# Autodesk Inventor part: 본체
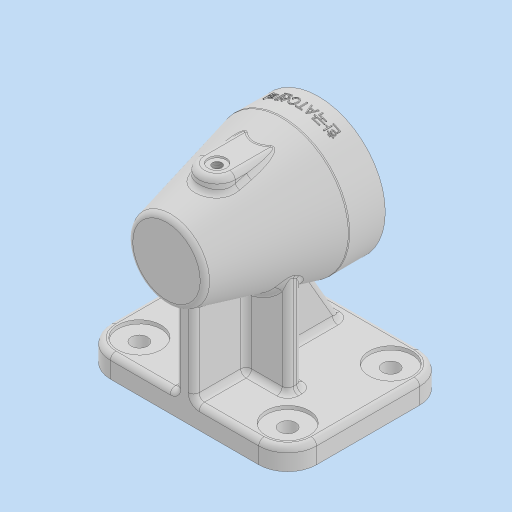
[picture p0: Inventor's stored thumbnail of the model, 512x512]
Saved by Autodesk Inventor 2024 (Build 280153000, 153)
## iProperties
Created: 2024-12
Part Number: 본체
Material: 일반
Document SubType Name: Modeling
Designer: user
Density: 1 g/cm^3
Appearance: 기본값
Author: user
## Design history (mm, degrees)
sketch "스케치11"
  geometry: L1 (0, 42)-(0, -42); L2 (0, 42)-(21, 42); L3 (21, 42)-(37, -22); L4 (37, -22)-(37, -42); L5 (37, -42)-(24.5, -42); L6 (23.5, -41)-(23.5, -24); L7 (23.5, -24)-(25.743, -24); L8 (30.606, -17.837)-(21.871, 18.698); L9 (18.953, 21)-(18.5, 21); L10 (17.5, 22)-(17.5, 30.7); L11 (17.2, 31)-(15.5, 31); L12 (15.5, 31)-(15.5, 31); L13 (12.5, 34)-(0, 34); L14 (17.5, 22)-(18.5, 21); L15 (23.5, -41)-(24.5, -42); L16 (24.5, -42)-(0, -42); A1 r 5 centre (25.743, -19) between (25.743, -24) and (30.606, -17.837); A2 r 0.3 centre (17.2, 30.7) between (17.5, 30.7) and (17.2, 31); A3 r 3 centre (18.953, 18) between (21.871, 18.698) and (18.953, 21); A4 r 3 centre (12.5, 31) between (15.5, 31) and (12.5, 34); 12 further points
  constraints: 32 end point, 8 perpendicular, 8 point on circle, 8 point on line, 8 tangent, 7 midpoint, 4 centre point, 2 vertical, 1 coincident, 1 horizontal, 1 parallel
  dimensions: "d29" = 84 distance of L1.start L1.end; "d30" = 74 diameter of L4 L1; "d31" = 42 diameter of L2.end L1; "d32" = 20 distance of L3.end L4.end; "d52" = 47 diameter of L6 L1; "d53" = 5 radius of A1; "d54" = 18 distance of point (23.5, -42) L6.end; "d56" = 35 diameter of point (17.5, 26.35) L1; "d57" = 31 diameter of point (15.5, 31) L1; "d58" = 0.3 radius of A2; "d59" = 10 distance from line of L9 point (16.35, 31); "d60" = 3 distance between parallel lines of L13 L11; "d62" = 3 radius of A3; "d63" = 5 distance from line of L3 point (26.239, 0.43); "d65" = 45 distance between parallel lines of L7 L9; "d66" = 3 radius of A4 (derived); "d67" = 1 distance of L10.start point (17.5, 21); "d68" = 1 distance of L9.end point (17.5, 21) (= d67); "d69" = 13.4469 deg angle of L1 L8; "d70" = 1 distance of L6.start point (23.5, -42); "d71" = 1 distance of L5.end point (23.5, -42) (= d70)
revolve "회전1" stored, may be unused: angle "d33" = 90 deg
node "작업 평면5"
sketch "스케치12"
  geometry: L1 (57, -57)-(-57, -57); L2 (-57, -57)-(-57, 32); L3 (-57, 32)-(57, 32); L4 (57, 32)-(57, -57); L5 (-37, -42)-(37, -42) reference; 2 further points
  constraints: 8 end point, 2 parallel, 1 horizontal, 1 midpoint, 1 perpendicular, 1 vertical alignment
  dimensions: "d35" = 15 distance between parallel lines of L5 L1; "d36" = 114 distance between parallel lines of L2 L4; "d37" = 89 distance of L1.end L2.end
extrude "돌출5" join sketch "스케치12" distance "d38" = 12; taper "d39" = 0 deg
revolve "회전2" stored, may be unused: angle "d72" = 90 deg
sketch "스케치18"
  geometry: L1 (-57, -32)-(57, -32) reference; L2 (-28, -3)-(28, -3); L3 (28, -3)-(28, 5); L4 (28, 5)-(-28, 5); L5 (-28, 5)-(-28, -3); 2 further points
  constraints: 8 end point, 2 parallel, 1 horizontal, 1 midpoint, 1 perpendicular, 1 vertical alignment
  dimensions: "d75" = 8 distance of L4.end L2.start; "d76" = 56 distance of L3.end L4.end; "d77" = 29 distance between parallel lines of L1 L2
extrude "돌출7" join sketch "스케치18" stored distance "d78" = 18; taper "d79" = 0 deg
sketch "스케치19"
  geometry: L1 (-37, -30.947)-(-70, -50); L2 (-70, -57)-(-70, 32) reference; L3 (-37, -22)-(-37, -42) reference; 1 further point
  constraints: 2 end point, 2 point on line
  dimensions: "d80" = 7 distance of L1.end L2.start; "d81" = 60 deg angle of L2 L1
feature "리브1" sketch "스케치19" dims "d82" = 1, "d83" = 10, "d84" = 0, "d85" = 0, "d86" = 1, "d87" = 1
sketch "스케치20"
  geometry: L1 (-82, 32)-(-70, 32) reference; L2 (-70, 32)-(-23.5, 32); L3 (-21, 42)-(-30.75, 3) reference; 1 further point
  constraints: 2 end point, 1 horizontal, 1 point on line
feature "리브2" sketch "스케치20" dims "d88" = 1, "d89" = 10, "d90" = 0, "d91" = 0, "d92" = 1, "d93" = 1
sketch "스케치21" dims "d94" = 57
  geometry: C1 r 24.5 at (0, 0) reference; C2 r 37 at (0, 0) reference; 2 further points
  constraints: 2 vertical alignment, 1 coincident, 2 other
hole "구멍1" sketch "스케치21" at (0, 28.5) diameter "d95" = 3.242; stored, may be unused: countersink angle "d99" = 90 deg, drill point angle "d101" = 118 deg; dims "d96" = 8, "d97" = 4, "d98" = 2, "d100" = 10
node "작업 평면6"
sketch "스케치22"
  geometry: L1 (-37, -42)-(37, -42) reference; L2 (16.733, -22)-(16.733, -42) reference; L3 (16.733, -42)-(-16.733, -42) reference; L4 (-16.733, -42)-(-16.733, -22) reference; L5 (10, 14)-(10, -11.928); L6 (-10, 14)-(-10, -11.928); L7 (5, 32)-(5, 3) reference; A1 r 10 centre (0, 14) between (10, 14) and (-10, 14); 1 further point
  constraints: 4 end point, 2 point on circle, 2 tangent, 1 centre point, 1 parallel, 1 vertical, 1 vertical alignment, 3 other
  dimensions: "d107" = 20 diameter of A1; "d108" = 56 distance from line of L1 A1.centre
extrude "돌출8" join sketch "스케치22" stored distance "d109" = 10; taper "d110" = 0 deg
fillet "모깎기1" dims "d111" = 3
fillet "모깎기2" dims "d112" = 3
sketch "스케치23"
  geometry: A1 r 7 centre (0, -14) between (-7, -14) and (7, -14) reference; 2 further points
  constraints: 1 coincident
hole "구멍2" sketch "스케치23" at (0, -14) diameter "d113" = 5.1881; stored, may be unused: countersink angle "d117" = 90 deg, drill point angle "d119" = 0 deg; dims "d114" = 12, "d115" = 10, "d116" = 1, "d118" = 17.1
fillet "모깎기3" dims "d120" = 16
sketch "스케치24"
  geometry: A1 r 16 centre (-41, -16) between (-57, -16) and (-41, -32) reference; A2 r 16 centre (41, -16) between (41, -32) and (57, -16) reference; A3 r 16 centre (41, 41) between (57, 41) and (41, 57) reference; A4 r 16 centre (-41, 41) between (-41, 57) and (-57, 41) reference; 5 further points
  constraints: 4 coincident
hole "구멍3" sketch "스케치24" at (41, 41), (41, -16), (-41, -16), (-41, 41) diameter "d121" = 9; stored, may be unused: countersink angle "d125" = 90 deg, drill point angle "d127" = 0 deg; dims "d122" = 12, "d123" = 24, "d124" = 2, "d126" = 8
fillet "모깎기4" dims "d128" = 3
fillet "모깎기5" dims "d129" = 3
fillet "모깎기6" dims "d130" = 3
fillet "모깎기7" dims "d131" = 3
node "작업 평면8"
sketch "스케치25"
  geometry: L1 (-37, -10)-(37, -10) reference; 2 further points
  constraints: 1 vertical alignment, 1 other
feature "엠보싱1" sketch "스케치25" dims "d29" = 84, "d30" = 74, "d31" = 42, "d32" = 20, "d52" = 47, "d53" = 5, "d54" = 18, "d56" = 35, "d57" = 31, "d58" = 0.3, "d59" = 10, "d60" = 3, "d62" = 3, "d63" = 5, "d65" = 45, "d66" = 3 (derived), "d67" = 1, "d68" = 1 (= d67), "d69" = 2.34693, "d70" = 1, "d71" = 1 (= d70), "d134" = 0.5, "d135" = 0
fillet "모깎기8" dims "d136" = 3
feature "Ϧ耀Ϩ耀Ϫ耀Ϭ耀Ϯ耀ϰ耀ϲ耀ϴ耀" dims "d29" = 84, "d30" = 74, "d31" = 42, "d32" = 20, "d33" = 90 deg, "d34" = -82, "d35" = 15, "d36" = 114, "d37" = 89, "d38" = 12, "d39" = 0, "d52" = 47, "d53" = 5, "d54" = 18, "d56" = 35, "d57" = 31, "d58" = 0.3, "d59" = 10, "d60" = 3, "d62" = 3, "d63" = 5, "d65" = 45, "d66" = 3 (derived), "d67" = 1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
node "솔리드3"
pattern_circular "원형 패턴1" dims angle "d103" = 360 deg
node "절단 모서리 투영1"
feature "A9D066F2-1C7D-4E18-AEED-F7BC21143FA4" dims "d121" = 9, "d122" = 12, "d123" = 24, "d124" = 2, "d125" = 90 deg, "d126" = 8, "d127" = 0
